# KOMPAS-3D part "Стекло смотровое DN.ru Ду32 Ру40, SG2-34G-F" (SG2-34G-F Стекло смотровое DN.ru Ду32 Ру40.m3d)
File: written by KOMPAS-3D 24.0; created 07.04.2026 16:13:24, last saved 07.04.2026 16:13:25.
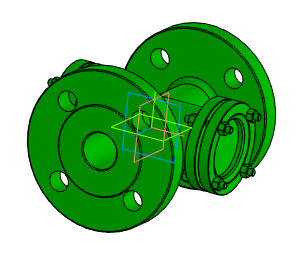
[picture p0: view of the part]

Document properties: Автор: Main; Полное имя файла: D:\DN.ru Аутсерс\Стекло смотровое DN.ru\SG2-34G-F Стекло смотровое DN.ru Ду32 Ру40\SG2-34G-F Стекло смотровое DN.ru Ду32 Ру40.m3d

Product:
- Body: Тело 1  | qty 1
    Масса: 6.03947
- Part/product: Стекло смотровое DN.ru Ду32 Ру40  | designation SG2-34G-F
    Масса: 6.2
    Раздел спецификации: Прочие изделия
    Примечание: D500-00082

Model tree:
1. Операция без истории:1

Expressions: SG2-34G-F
